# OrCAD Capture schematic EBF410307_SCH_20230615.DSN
size A4; title: 野火_鲁班猫40pin排针测试板; rev: V1.0; note: 鲁班猫40pin排针测试板; note: https://yehuosm.tmall.com
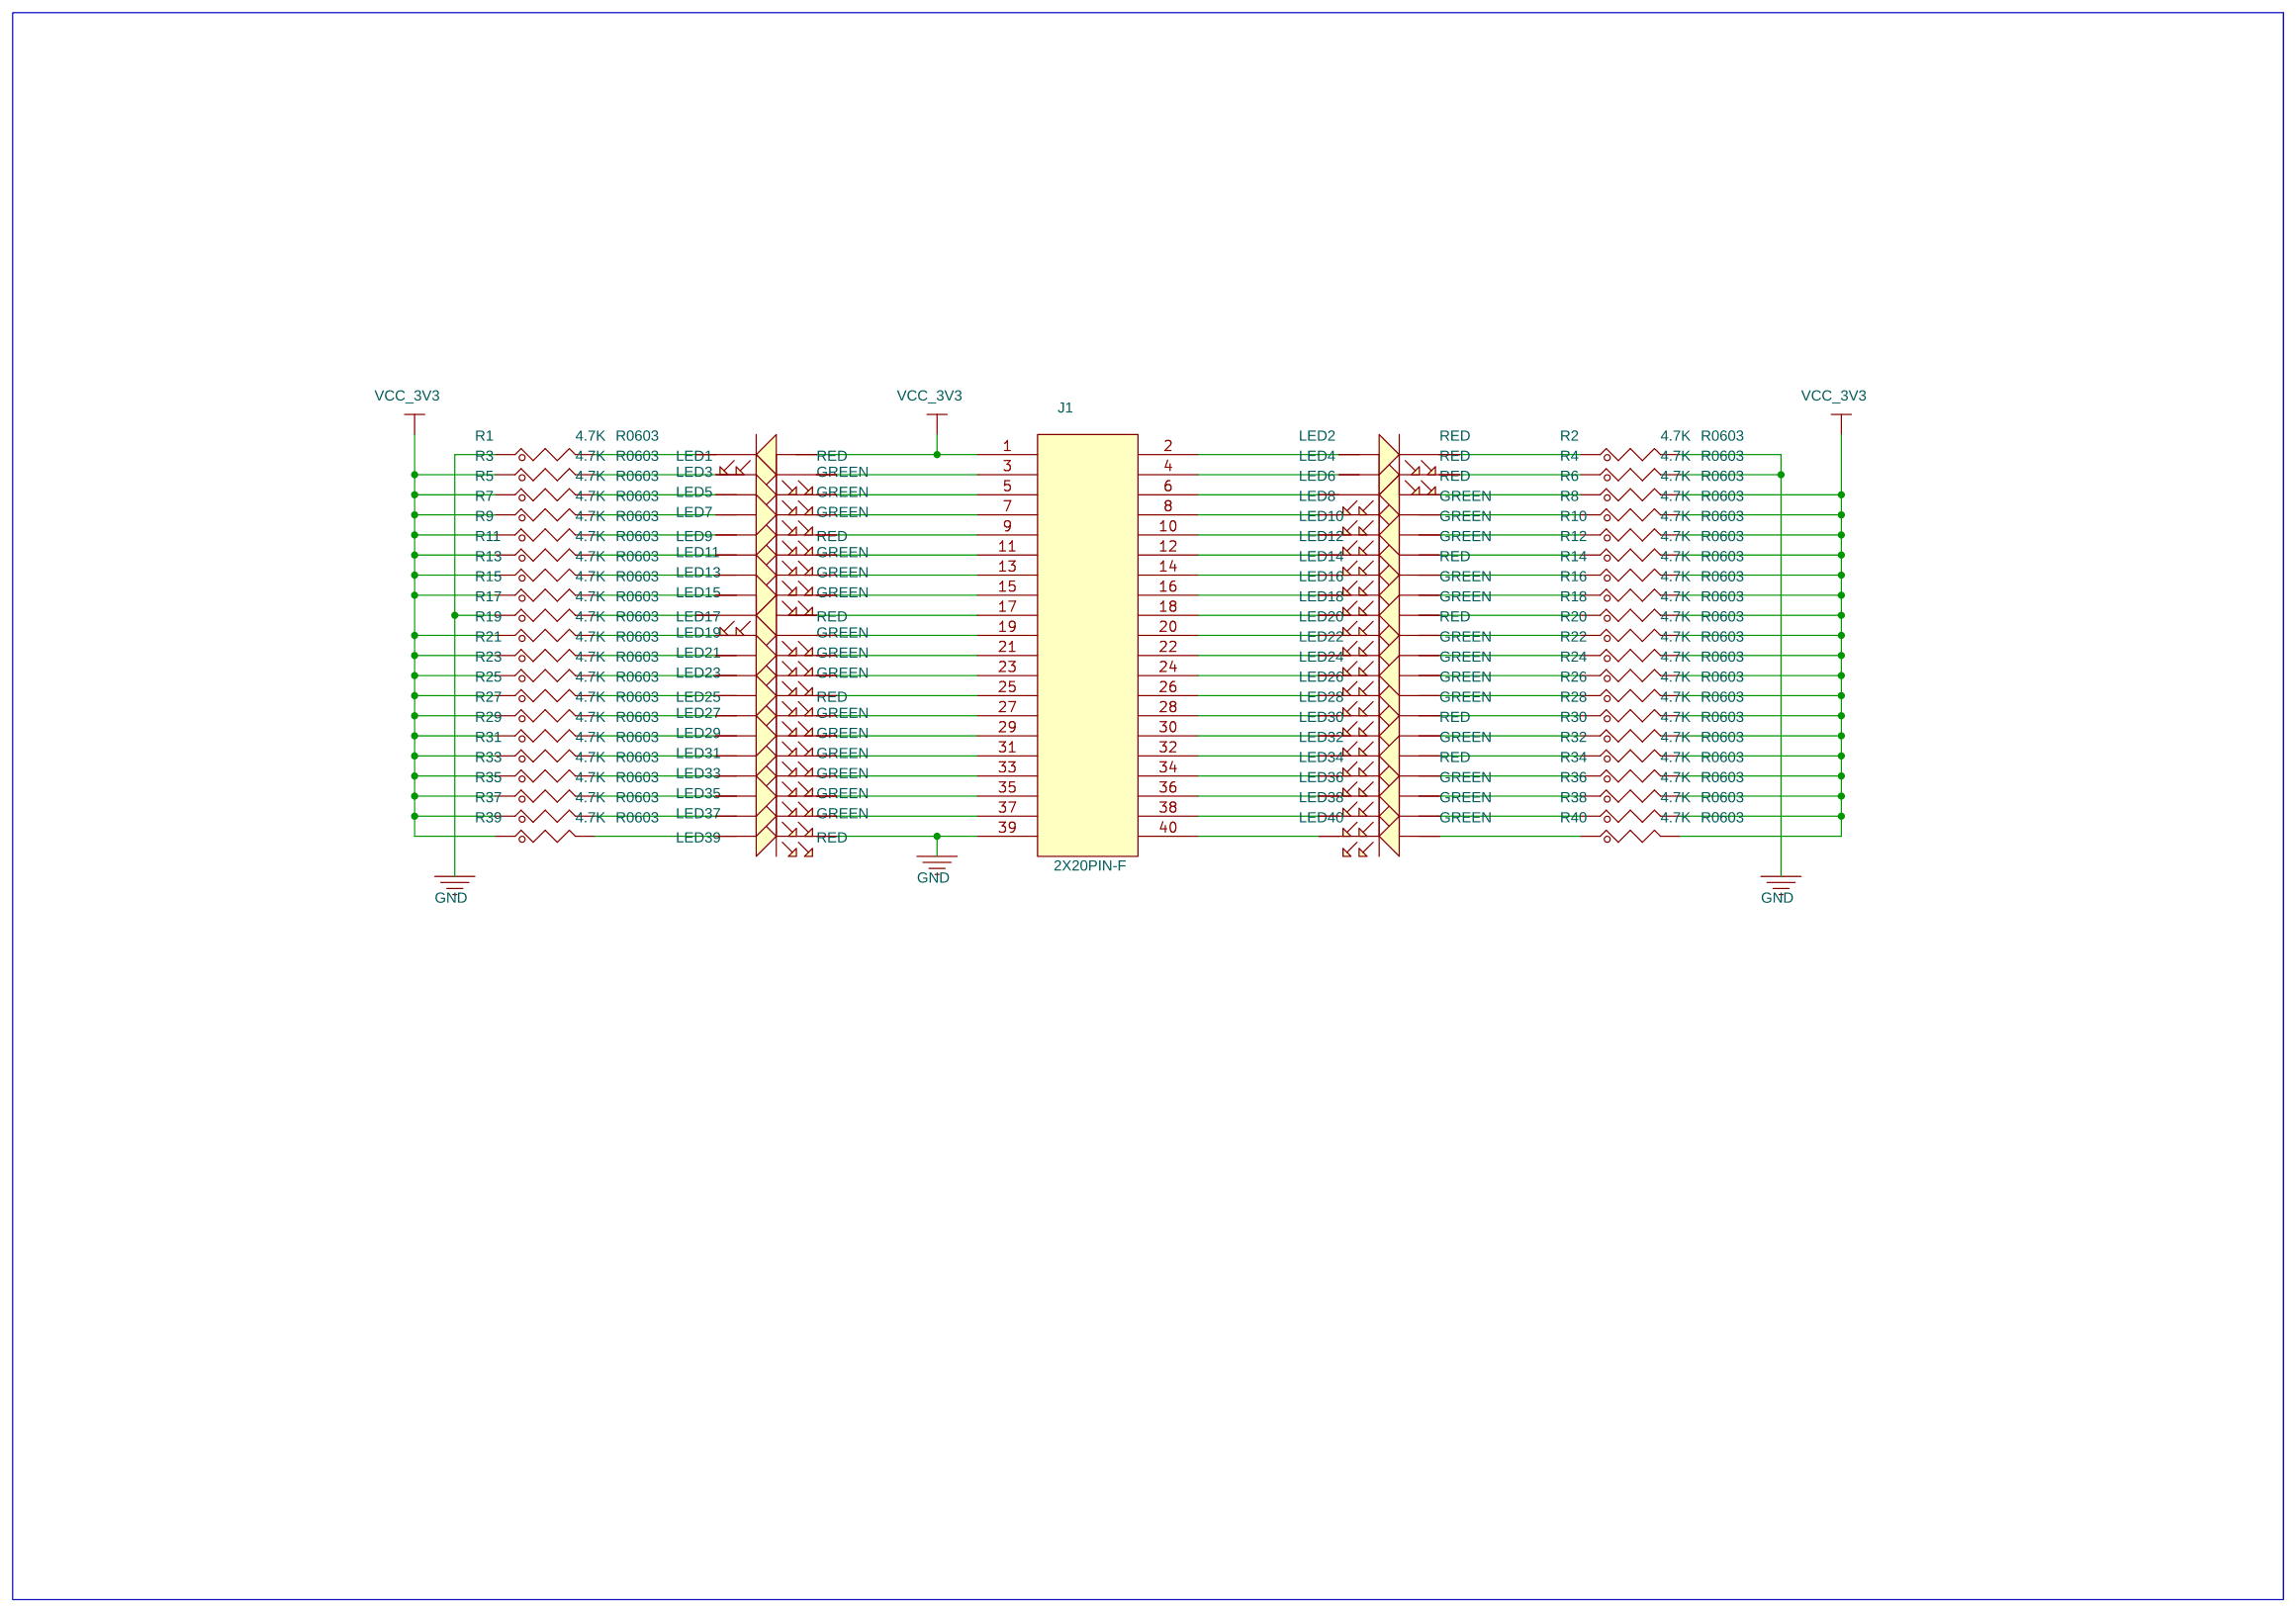
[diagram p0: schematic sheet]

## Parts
J1  2X20PIN-F  [dip-2x20_2p54]
LED1  RED  [LED0603]
LED2  RED  [LED0603]
LED3  GREEN  [LED0603]
LED4  RED  [LED0603]
LED5  GREEN  [LED0603]
LED6  RED  [LED0603]
LED7  GREEN  [LED0603]
LED8  GREEN  [LED0603]
LED9  RED  [LED0603]
LED10  GREEN  [LED0603]
LED11  GREEN  [LED0603]
LED12  GREEN  [LED0603]
LED13  GREEN  [LED0603]
LED14  RED  [LED0603]
LED15  GREEN  [LED0603]
LED16  GREEN  [LED0603]
LED17  RED  [LED0603]
LED18  GREEN  [LED0603]
LED19  GREEN  [LED0603]
LED20  RED  [LED0603]
LED21  GREEN  [LED0603]
LED22  GREEN  [LED0603]
LED23  GREEN  [LED0603]
LED24  GREEN  [LED0603]
LED25  RED  [LED0603]
LED26  GREEN  [LED0603]
LED27  GREEN  [LED0603]
LED28  GREEN  [LED0603]
LED29  GREEN  [LED0603]
LED30  RED  [LED0603]
LED31  GREEN  [LED0603]
LED32  GREEN  [LED0603]
LED33  GREEN  [LED0603]
LED34  RED  [LED0603]
LED35  GREEN  [LED0603]
LED36  GREEN  [LED0603]
LED37  GREEN  [LED0603]
LED38  GREEN  [LED0603]
LED39  RED  [LED0603]
LED40  GREEN  [LED0603]
R1  4.7K  [R0603]
R2  4.7K  [R0603]
R3  4.7K  [R0603]
R4  4.7K  [R0603]
R5  4.7K  [R0603]
R6  4.7K  [R0603]
R7  4.7K  [R0603]
R8  4.7K  [R0603]
R9  4.7K  [R0603]
R10  4.7K  [R0603]
R11  4.7K  [R0603]
R12  4.7K  [R0603]
R13  4.7K  [R0603]
R14  4.7K  [R0603]
R15  4.7K  [R0603]
R16  4.7K  [R0603]
R17  4.7K  [R0603]
R18  4.7K  [R0603]
R19  4.7K  [R0603]
R20  4.7K  [R0603]
R21  4.7K  [R0603]
R22  4.7K  [R0603]
R23  4.7K  [R0603]
R24  4.7K  [R0603]
R25  4.7K  [R0603]
R26  4.7K  [R0603]
R27  4.7K  [R0603]
R28  4.7K  [R0603]
R29  4.7K  [R0603]
R30  4.7K  [R0603]
R31  4.7K  [R0603]
R32  4.7K  [R0603]
R33  4.7K  [R0603]
R34  4.7K  [R0603]
R35  4.7K  [R0603]
R36  4.7K  [R0603]
R37  4.7K  [R0603]
R38  4.7K  [R0603]
R39  4.7K  [R0603]
R40  4.7K  [R0603]

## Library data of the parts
J1 = 2X20PIN: 规格: 排母 总PIN数40 间距2.54mm 直插; 规格书: 博穆精密_排母.pdf; 类别: 直插双排排母; 生命周期: 量产; 条码: EBF29020049
LED1 LED2 LED4 LED6 LED9 LED14 LED17 LED20 LED25 LED30 LED34 LED39 = LED: 规格: 贴片LED RED 正向电流30mA 反向电压9V 功率消耗350mW 0603; 规格编号: 35B00617LGY-RED; 规格书: LED0603-RED.pdf; 类别: 贴片LED; 品牌: 亿光; 生命周期: 量产; 条码: EBF29140007
LED3 LED5 LED7 LED8 LED10-LED13 LED15 LED16 LED18 LED19 LED21-LED24 LED26-LED29 LED31-LED33 LED35-LED38 LED40 = LED: 规格: 贴片LED GREEN 正向电流20mA 0603 正贴; 规格编号: EL0603/GHC-C01/DT; 规格书: LED0603-RED.pdf; 类别: 贴片LED; 品牌: 亿光; 生命周期: 量产; 条码: EBF29140043
R1-R40 = RES: 规格: 贴片电阻4.7K 1% 1/10W 0603; 规格编号: 0603WAF4701T5E; 规格书: 厚声-无铅厚膜电阻.pdf; 价格: 0.005382; 类别: 贴片电阻0603; 品牌: 厚声; 生命周期: 量产; 条码: EBF29070071

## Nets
GND: J1.39 LED39.1(CATHODE) R1.1 R2.2 R4.2 R17.1
VCC_3V3: J1.1 LED1.2(ANODE) R3.1 R5.1 R6.2 R7.1 R8.2 R9.1 R10.2 R11.1 R12.2 R13.1 R14.2 R15.1 R16.2 R18.2 R19.1 R20.2 R21.1 R22.2 R23.1 R24.2 R25.1 R26.2 R27.1 R28.2 R29.1 R30.2 R31.1 R32.2 R33.1 R34.2 R35.1 R36.2 R37.1 R38.2 R39.1 R40.2
N16483237: J1.2 LED2.2(ANODE)
N16483392: LED2.1(CATHODE) R2.1
N16483434: J1.3 LED3.1(CATHODE)
N16483438: LED3.2(ANODE) R3.2
N16483442: LED1.1(CATHODE) R1.2
N16483540: J1.4 LED4.2(ANODE)
N16483576: LED4.1(CATHODE) R4.1
N16484980: J1.5 LED5.1(CATHODE)
N16484992: J1.7 LED7.1(CATHODE)
N16485004: J1.9 LED9.1(CATHODE)
N16485016: J1.11 LED11.1(CATHODE)
N16485028: J1.13 LED13.1(CATHODE)
N16485040: J1.15 LED15.1(CATHODE)
N16485229: J1.17 LED17.2(ANODE)
N16485267: J1.19 LED19.1(CATHODE)
N16485335: J1.21 LED21.1(CATHODE)
N16485347: J1.23 LED23.1(CATHODE)
N16485387: J1.27 LED27.1(CATHODE)
N16485391: J1.29 LED29.1(CATHODE)
N16485403: J1.31 LED31.1(CATHODE)
N16485415: J1.33 LED33.1(CATHODE)
N16485427: J1.35 LED35.1(CATHODE)
N16485439: J1.37 LED37.1(CATHODE)
N16485492: J1.6 LED6.1(CATHODE)
N16485496: J1.8 LED8.1(CATHODE)
N16485534: J1.25 LED25.1(CATHODE)
N16485584: J1.10 LED10.1(CATHODE)
N16485596: J1.12 LED12.1(CATHODE)
N16485608: J1.14 LED14.1(CATHODE)
N16485620: J1.16 LED16.1(CATHODE)
N16485632: J1.18 LED18.1(CATHODE)
N16485644: J1.20 LED20.1(CATHODE)
N16485656: J1.22 LED22.1(CATHODE)
N16485668: J1.24 LED24.1(CATHODE)
N16485680: J1.26 LED26.1(CATHODE)
N16485692: J1.28 LED28.1(CATHODE)
N16485704: J1.30 LED30.1(CATHODE)
N16485716: J1.32 LED32.1(CATHODE)
N16485728: J1.34 LED34.1(CATHODE)
N16485740: J1.36 LED36.1(CATHODE)
N16485752: J1.38 LED38.1(CATHODE)
N16485764: J1.40 LED40.1(CATHODE)
N16551066: LED5.2(ANODE) R5.2
N16551078: LED7.2(ANODE) R7.2
N16551090: LED9.2(ANODE) R9.2
N16551102: LED11.2(ANODE) R11.2
N16551114: LED13.2(ANODE) R13.2
N16551126: LED15.2(ANODE) R15.2
N16551138: LED17.1(CATHODE) R17.2
N16551155: LED19.2(ANODE) R19.2
N16551167: LED21.2(ANODE) R21.2
N16551179: LED23.2(ANODE) R23.2
N16551191: LED25.2(ANODE) R25.2
N16551203: LED27.2(ANODE) R27.2
N16551215: LED29.2(ANODE) R29.2
N16551227: LED31.2(ANODE) R31.2
N16551239: LED33.2(ANODE) R33.2
N16551251: LED35.2(ANODE) R35.2
N16551263: LED37.2(ANODE) R37.2
N16551275: LED39.2(ANODE) R39.2
N16551283: LED6.2(ANODE) R6.1
N16551295: LED8.2(ANODE) R8.1
N16551307: LED10.2(ANODE) R10.1
N16551319: LED12.2(ANODE) R12.1
N16551331: LED14.2(ANODE) R14.1
N16551343: LED16.2(ANODE) R16.1
N16551355: LED18.2(ANODE) R18.1
N16551367: LED20.2(ANODE) R20.1
N16551379: LED22.2(ANODE) R22.1
N16551391: LED24.2(ANODE) R24.1
N16551403: LED26.2(ANODE) R26.1
N16551415: LED28.2(ANODE) R28.1
N16551427: LED30.2(ANODE) R30.1
N16551439: LED32.2(ANODE) R32.1
N16551451: LED34.2(ANODE) R34.1
N16551463: LED36.2(ANODE) R36.1
N16551475: LED38.2(ANODE) R38.1
N16551487: LED40.2(ANODE) R40.1
